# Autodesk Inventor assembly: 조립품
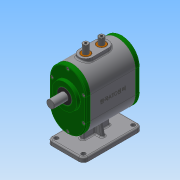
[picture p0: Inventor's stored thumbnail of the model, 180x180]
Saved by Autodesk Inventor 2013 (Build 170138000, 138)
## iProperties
Created: 2018-10
Part Number: 조립품
Document SubType Name: Assembly
Designer: Administrator
Mass: 2684.8 g
Surface Area: 2130.53 cm^2
Volume: 748.302 cm^3
Density: 3.58785 g/cm^3
Author: Administrator
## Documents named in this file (15)
- C:\Users\Administrator\Desktop\381007V1021\답안조립품.iam
- C:\Users\Administrator\Desktop\381007V1021\본체.ipt
- C:\Users\Administrator\Desktop\381007V1021\가변스프링1.ipt
- C:\Users\Administrator\Desktop\381007V1021\가변스프링2.ipt
- C:\Users\Administrator\Desktop\381007V1021\뒤커버.ipt
- C:\Users\Administrator\Desktop\381007V1021\메인축.ipt
- C:\Users\Administrator\Desktop\381007V1021\베어링 608.ipt
- C:\Users\Administrator\Desktop\381007V1021\베어링 6003.ipt
- C:\Users\Administrator\Desktop\381007V1021\볼트 M4.ipt
- C:\Users\Administrator\Desktop\381007V1021\부시.ipt
- C:\Users\Administrator\Desktop\381007V1021\서브축.ipt
- C:\Users\Administrator\Desktop\381007V1021\슬라이더.ipt
- C:\Users\Administrator\Desktop\381007V1021\앞커버.ipt
- C:\Users\Administrator\Desktop\381007V1021\오일실 8 22 7.ipt
- C:\Users\Administrator\Desktop\381007V1021\오일실 17 32 8.ipt
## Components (2 placed, 2 different names)
1. 가변스프링1:1
2. 가변스프링2:1
